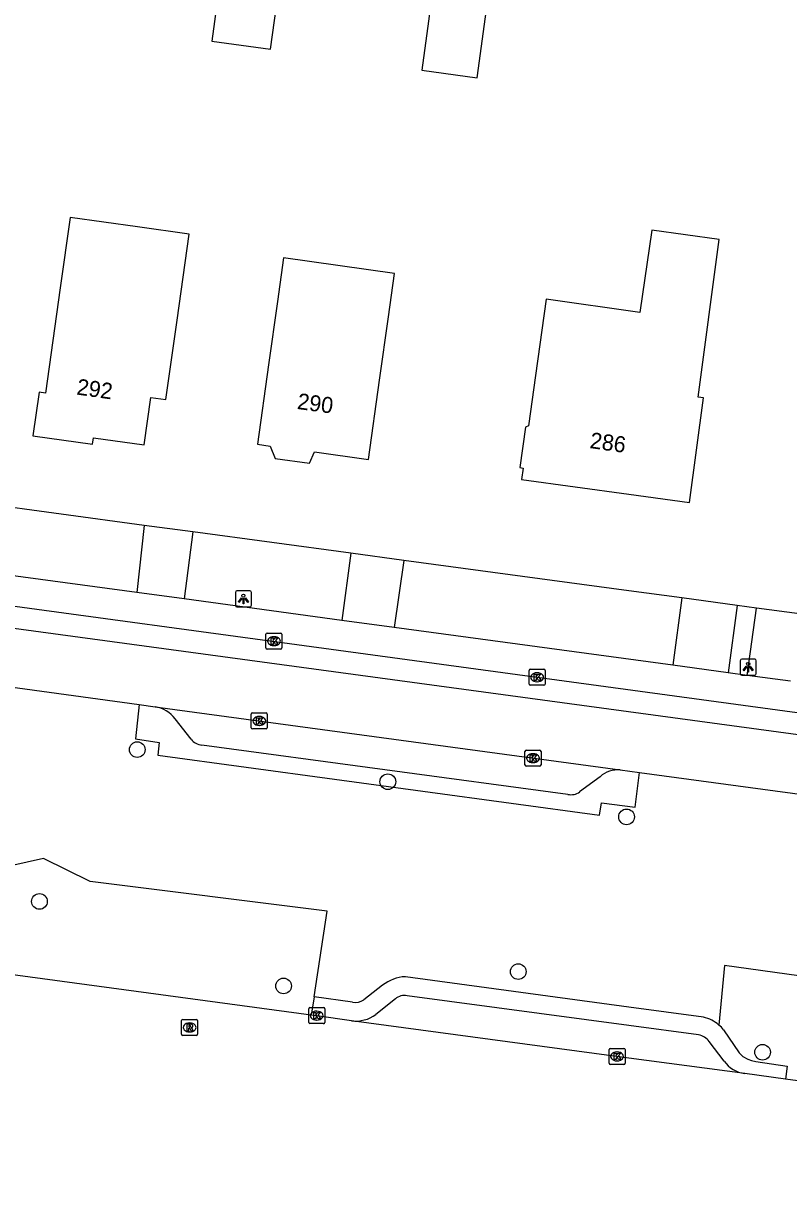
# Model space of a CAD drawing. Extents: x 161696 to 162377, y 380761 to 381673.
# Drawn here: x 161962.2 to 162010, y 380780.2 to 380852.7 of the extents above; entities that cross this region are included whole.
import ezdxf

# ---------------------------------------------------------------- set-up
doc = ezdxf.new("R2010")
doc.units = 0
for name, color, linetype in [('IMGEO_Berm_groen', 7, 'Continuous'), ('IMGEO_Boom', 7, 'Continuous'), ('IMGEO_Kolk', 7, 'Continuous'), ('IMGEO_Lichtpunt', 7, 'Continuous'), ('IMGEO_Pand', 7, 'Continuous'), ('IMGEO_Pand_nummerreeks', 7, 'Continuous'), ('IMGEO_Rijbaan_lokaal_gesloten', 7, 'Continuous'), ('IMGEO_Rioolput', 7, 'Continuous'), ('IMGEO_Voetpad_open', 7, 'Continuous')]:
    doc.layers.add(name, color=color, linetype=linetype)

msp = doc.modelspace()

# ---------------------------------------------------------------- linework, layer by layer
at = {"layer": 'IMGEO_Berm_groen'}
for points in [[(161980.351, 380791.965), (161981.166, 380797.303), (161966.376, 380799.167), (161963.473, 380800.601), (161960.395, 380799.921), (161944.127, 380801.972), (161946.701, 380796.522)], [(162042.929, 380788.793), (162005.959, 380793.923), (162005.619, 380790.206)]]:
    msp.add_lwpolyline(points, dxfattribs=at)
at = {"layer": 'IMGEO_Boom'}
for centre in [(161969.319, 380807.392), (161984.957, 380805.39), (161999.854, 380803.197), (161963.219, 380797.918), (161993.096, 380793.539), (161978.451, 380792.645), (162008.342, 380788.51)]:
    msp.add_circle(centre, 0.489, dxfattribs=at)
at = {"layer": 'IMGEO_Kolk'}
for p, q in [((161977.351, 380813.735), (161977.351, 380814.587)), ((161977.426, 380814.661), (161978.278, 380814.661)), ((161977.839, 380814.441), (161977.864, 380814.441)), ((161978.352, 380814.587), (161978.352, 380813.735)), ((161978.278, 380813.661), (161977.426, 380813.661)), ((161977.862, 380813.881), (161977.837, 380813.881)), ((161993.772, 380811.48), (161993.772, 380812.332)), ((161993.847, 380812.406), (161994.699, 380812.406)), ((161994.26, 380812.186), (161994.285, 380812.186)), ((161994.773, 380812.332), (161994.773, 380811.48)), ((161994.699, 380811.406), (161993.847, 380811.406)), ((161994.283, 380811.626), (161994.258, 380811.626)), ((161976.435, 380808.755), (161976.435, 380809.607)), ((161976.51, 380809.681), (161977.362, 380809.681)), ((161976.923, 380809.461), (161976.948, 380809.461)), ((161977.436, 380809.607), (161977.436, 380808.755)), ((161977.362, 380808.681), (161976.51, 380808.681)), ((161976.946, 380808.901), (161976.921, 380808.901)), ((161993.515, 380806.433), (161993.515, 380807.285)), ((161993.59, 380807.359), (161994.442, 380807.359)), ((161994.003, 380807.139), (161994.028, 380807.139)), ((161994.516, 380807.285), (161994.516, 380806.433)), ((161994.442, 380806.359), (161993.59, 380806.359)), ((161994.026, 380806.579), (161994.001, 380806.579)), ((161980.02, 380790.366), (161980.02, 380791.218)), ((161980.095, 380791.292), (161980.947, 380791.292)), ((161980.508, 380791.072), (161980.533, 380791.072)), ((161981.021, 380791.218), (161981.021, 380790.366)), ((161980.947, 380790.292), (161980.095, 380790.292)), ((161980.531, 380790.512), (161980.506, 380790.512)), ((161998.761, 380787.822), (161998.761, 380788.674)), ((161998.836, 380788.748), (161999.688, 380788.748)), ((161999.249, 380788.528), (161999.274, 380788.528)), ((161999.762, 380788.674), (161999.762, 380787.822)), ((161999.688, 380787.748), (161998.836, 380787.748)), ((161999.272, 380787.968), (161999.247, 380787.968))]:
    msp.add_line(p, q, dxfattribs=at)
for points in [[(161977.351, 380813.735), (161977.351, 380814.587)], [(161977.426, 380814.661), (161978.278, 380814.661)], [(161977.672, 380814.361), (161977.795, 380814.361), (161977.795, 380814.21), (161977.925, 380814.361), (161978.089, 380814.361), (161977.943, 380814.21), (161978.096, 380813.961), (161977.944, 380813.961), (161977.859, 380814.125), (161977.795, 380814.058), (161977.795, 380813.961), (161977.672, 380813.961), (161977.672, 380814.361)], [(161978.352, 380814.587), (161978.352, 380813.735)], [(161978.278, 380813.661), (161977.426, 380813.661)], [(161993.772, 380811.48), (161993.772, 380812.332)], [(161993.847, 380812.406), (161994.699, 380812.406)], [(161994.093, 380812.106), (161994.216, 380812.106), (161994.216, 380811.955), (161994.346, 380812.106), (161994.51, 380812.106), (161994.364, 380811.955), (161994.517, 380811.706), (161994.365, 380811.706), (161994.28, 380811.87), (161994.216, 380811.803), (161994.216, 380811.706), (161994.093, 380811.706), (161994.093, 380812.106)], [(161994.773, 380812.332), (161994.773, 380811.48)], [(161994.699, 380811.406), (161993.847, 380811.406)], [(161976.435, 380808.755), (161976.435, 380809.607)], [(161976.51, 380809.681), (161977.362, 380809.681)], [(161976.756, 380809.381), (161976.879, 380809.381), (161976.879, 380809.23), (161977.009, 380809.381), (161977.173, 380809.381), (161977.027, 380809.23), (161977.18, 380808.981), (161977.028, 380808.981), (161976.943, 380809.145), (161976.879, 380809.078), (161976.879, 380808.981), (161976.756, 380808.981), (161976.756, 380809.381)], [(161977.436, 380809.607), (161977.436, 380808.755)], [(161977.362, 380808.681), (161976.51, 380808.681)], [(161993.515, 380806.433), (161993.515, 380807.285)], [(161993.59, 380807.359), (161994.442, 380807.359)], [(161993.836, 380807.059), (161993.959, 380807.059), (161993.959, 380806.908), (161994.089, 380807.059), (161994.253, 380807.059), (161994.107, 380806.908), (161994.26, 380806.659), (161994.108, 380806.659), (161994.023, 380806.823), (161993.959, 380806.756), (161993.959, 380806.659), (161993.836, 380806.659), (161993.836, 380807.059)], [(161994.516, 380807.285), (161994.516, 380806.433)], [(161994.442, 380806.359), (161993.59, 380806.359)], [(161980.02, 380790.366), (161980.02, 380791.218)], [(161980.095, 380791.292), (161980.947, 380791.292)], [(161980.341, 380790.992), (161980.464, 380790.992), (161980.464, 380790.841), (161980.594, 380790.992), (161980.758, 380790.992), (161980.612, 380790.841), (161980.765, 380790.592), (161980.613, 380790.592), (161980.528, 380790.756), (161980.464, 380790.689), (161980.464, 380790.592), (161980.341, 380790.592), (161980.341, 380790.992)], [(161981.021, 380791.218), (161981.021, 380790.366)], [(161980.947, 380790.292), (161980.095, 380790.292)], [(161998.761, 380787.822), (161998.761, 380788.674)], [(161998.836, 380788.748), (161999.688, 380788.748)], [(161999.082, 380788.448), (161999.205, 380788.448), (161999.205, 380788.297), (161999.335, 380788.448), (161999.499, 380788.448), (161999.353, 380788.297), (161999.506, 380788.048), (161999.354, 380788.048), (161999.269, 380788.212), (161999.205, 380788.145), (161999.205, 380788.048), (161999.082, 380788.048), (161999.082, 380788.448)], [(161999.762, 380788.674), (161999.762, 380787.822)], [(161999.688, 380787.748), (161998.836, 380787.748)]]:
    msp.add_lwpolyline(points, dxfattribs=at)
for centre, start, end in [((161977.428, 380814.585), 91.55205, 178.44795), ((161977.428, 380814.585), 91.55205, 178.44795), ((161978.276, 380814.585), 1.55205, 88.44795), ((161978.276, 380814.585), 1.55205, 88.44795), ((161977.428, 380813.737), 181.55205, 268.44795), ((161977.428, 380813.737), 181.55205, 268.44795), ((161978.276, 380813.737), 271.55205, 358.44795), ((161978.276, 380813.737), 271.55205, 358.44795), ((161993.849, 380812.33), 91.55205, 178.44795), ((161993.849, 380812.33), 91.55205, 178.44795), ((161994.697, 380812.33), 1.55205, 88.44795), ((161994.697, 380812.33), 1.55205, 88.44795), ((161993.849, 380811.482), 181.55205, 268.44795), ((161993.849, 380811.482), 181.55205, 268.44795), ((161994.697, 380811.482), 271.55205, 358.44795), ((161994.697, 380811.482), 271.55205, 358.44795), ((161976.512, 380809.605), 91.55205, 178.44795), ((161976.512, 380809.605), 91.55205, 178.44795), ((161977.36, 380809.605), 1.55205, 88.44795), ((161977.36, 380809.605), 1.55205, 88.44795), ((161976.512, 380808.757), 181.55205, 268.44795), ((161976.512, 380808.757), 181.55205, 268.44795), ((161977.36, 380808.757), 271.55205, 358.44795), ((161977.36, 380808.757), 271.55205, 358.44795), ((161993.592, 380807.283), 91.55205, 178.44795), ((161993.592, 380807.283), 91.55205, 178.44795), ((161994.44, 380807.283), 1.55205, 88.44795), ((161994.44, 380807.283), 1.55205, 88.44795), ((161993.592, 380806.435), 181.55205, 268.44795), ((161993.592, 380806.435), 181.55205, 268.44795), ((161994.44, 380806.435), 271.55205, 358.44795), ((161994.44, 380806.435), 271.55205, 358.44795), ((161980.097, 380791.216), 91.55205, 178.44795), ((161980.097, 380791.216), 91.55205, 178.44795), ((161980.945, 380791.216), 1.55205, 88.44795), ((161980.945, 380791.216), 1.55205, 88.44795), ((161980.097, 380790.368), 181.55205, 268.44795), ((161980.097, 380790.368), 181.55205, 268.44795), ((161980.945, 380790.368), 271.55205, 358.44795), ((161980.945, 380790.368), 271.55205, 358.44795), ((161998.838, 380788.672), 91.55205, 178.44795), ((161998.838, 380788.672), 91.55205, 178.44795), ((161999.686, 380788.672), 1.55205, 88.44795), ((161999.686, 380788.672), 1.55205, 88.44795), ((161998.838, 380787.824), 181.55205, 268.44795), ((161998.838, 380787.824), 181.55205, 268.44795), ((161999.686, 380787.824), 271.55205, 358.44795), ((161999.686, 380787.824), 271.55205, 358.44795)]:
    msp.add_arc(centre, 0.0765, start, end, dxfattribs=at)
for centre, major_axis, ratio, start_param, end_param in [((161977.838, 380814.161), (-0.387, 0.002), 0.722429, 4.712389, 7.853982), ((161977.863, 380814.161), (-0.39, 0.002), 0.717154, 1.570796, 4.712389), ((161994.259, 380811.906), (-0.387, 0.002), 0.722429, 4.712389, 7.853982), ((161994.284, 380811.906), (-0.39, 0.002), 0.717154, 1.570796, 4.712389), ((161976.922, 380809.181), (-0.387, 0.002), 0.722429, 4.712389, 7.853982), ((161976.947, 380809.181), (-0.39, 0.002), 0.717154, 1.570796, 4.712389), ((161994.002, 380806.859), (-0.387, 0.002), 0.722429, 4.712389, 7.853982), ((161994.027, 380806.859), (-0.39, 0.002), 0.717154, 1.570796, 4.712389), ((161980.507, 380790.792), (-0.387, 0.002), 0.722429, 4.712389, 7.853982), ((161980.532, 380790.792), (-0.39, 0.002), 0.717154, 1.570796, 4.712389), ((161999.248, 380788.248), (-0.387, 0.002), 0.722429, 4.712389, 7.853982), ((161999.273, 380788.248), (-0.39, 0.002), 0.717154, 1.570796, 4.712389)]:
    msp.add_ellipse(centre, major_axis=major_axis, ratio=ratio, start_param=start_param, end_param=end_param, dxfattribs=at)
at = {"layer": 'IMGEO_Lichtpunt'}
for p, q in [((161975.444, 380817.204), (161975.444, 380816.397)), ((161975.444, 380817.204), (161975.444, 380816.397)), ((161976.346, 380817.299), (161975.538, 380817.299)), ((161976.346, 380817.299), (161975.538, 380817.299)), ((161976.44, 380816.397), (161976.44, 380817.204)), ((161976.44, 380816.397), (161976.44, 380817.204)), ((161975.538, 380816.303), (161976.346, 380816.303)), ((161975.538, 380816.303), (161976.346, 380816.303)), ((162006.949, 380812.94), (162006.949, 380812.133)), ((162006.949, 380812.94), (162006.949, 380812.133)), ((162007.851, 380813.035), (162007.043, 380813.035)), ((162007.851, 380813.035), (162007.043, 380813.035)), ((162007.945, 380812.133), (162007.945, 380812.94)), ((162007.945, 380812.133), (162007.945, 380812.94)), ((162007.043, 380812.039), (162007.851, 380812.039)), ((162007.043, 380812.039), (162007.851, 380812.039))]:
    msp.add_line(p, q, dxfattribs=at)
for points in [[(161975.818, 380816.868), (161975.857, 380816.84), (161975.669, 380816.578), (161975.631, 380816.605), (161975.818, 380816.868)], [(161975.92, 380816.82), (161975.967, 380816.82), (161975.967, 380816.498), (161975.92, 380816.498), (161975.92, 380816.82)], [(161976.03, 380816.84), (161976.068, 380816.867), (161976.255, 380816.605), (161976.216, 380816.577), (161976.03, 380816.84)], [(162007.323, 380812.604), (162007.362, 380812.576), (162007.174, 380812.314), (162007.136, 380812.341), (162007.323, 380812.604)], [(162007.425, 380812.556), (162007.472, 380812.556), (162007.472, 380812.234), (162007.425, 380812.234), (162007.425, 380812.556)], [(162007.535, 380812.576), (162007.573, 380812.603), (162007.76, 380812.341), (162007.721, 380812.313), (162007.535, 380812.576)]]:
    msp.add_lwpolyline(points, dxfattribs=at)
for centre in [(161975.943, 380817.002), (162007.448, 380812.738)]:
    msp.add_circle(centre, 0.0994, dxfattribs=at)
for centre, start, end in [((161975.538, 380817.204), 90, 180), ((161975.538, 380817.204), 90, 180), ((161976.346, 380817.204), 0, 90), ((161976.346, 380817.204), 0, 90), ((161975.538, 380816.397), 180, 270), ((161975.538, 380816.397), 180, 270), ((161976.346, 380816.397), 270, 0), ((161976.346, 380816.397), 270, 360), ((162007.043, 380812.94), 90, 180), ((162007.043, 380812.94), 90, 180), ((162007.851, 380812.94), 0, 90), ((162007.851, 380812.94), 0, 90), ((162007.043, 380812.133), 180, 270), ((162007.043, 380812.133), 180, 270), ((162007.851, 380812.133), 270, 0), ((162007.851, 380812.133), 270, 360)]:
    msp.add_arc(centre, 0.0946, start, end, dxfattribs=at)
at = {"layer": 'IMGEO_Pand'}
for points in [[(161977.634, 380851.095), (161978.48, 380857.235), (161974.814, 380857.747), (161973.969, 380851.607), (161977.634, 380851.095)], [(161990.529, 380849.306), (161991.36, 380855.436), (161987.912, 380855.918), (161987.081, 380849.788), (161990.529, 380849.306)], [(161971.806, 380834.194), (161972.558, 380839.55), (161969.325, 380840.004), (161965.132, 380840.593), (161964.516, 380836.203), (161963.593, 380829.634), (161963.194, 380829.69), (161962.813, 380826.98), (161966.534, 380826.458), (161966.59, 380826.857), (161969.76, 380826.411), (161970.176, 380829.373), (161971.111, 380829.242), (161971.806, 380834.194)], [(162001.423, 380839.8), (162000.684, 380834.664), (161994.84, 380835.505), (161994.172, 380830.733), (161993.732, 380827.592), (161993.549, 380827.518), (161993.193, 380824.987), (161993.405, 380824.957), (161993.306, 380824.253), (162000, 380823.327), (162003.783, 380822.804), (162004.663, 380829.338), (162004.314, 380829.385), (162005.639, 380839.233), (162001.423, 380839.8)], [(161984.446, 380830.454), (161984.999, 380834.395), (161985.38, 380837.107), (161978.444, 380838.082), (161978.062, 380835.362), (161977.519, 380831.395), (161976.823, 380826.443), (161977.607, 380826.333), (161977.918, 380825.562), (161980.069, 380825.26), (161980.383, 380825.975), (161983.75, 380825.502), (161984.446, 380830.454)]]:
    msp.add_lwpolyline(points, dxfattribs=at)
at = {"layer": 'IMGEO_Rijbaan_lokaal_gesloten'}
for points in [[(162234.771, 380780.432), (162229.289, 380780.178), (162226.418, 380780.403), (162192.055, 380785.129), (162178.941, 380786.895), (162173.589, 380787.538), (162153.114, 380788.982), (161814.137, 380834.931)], [(161920.649, 380821.91), (162019.525, 380808.483)], [(161940.415, 380814.186), (161969.449, 380810.213)], [(161969.449, 380810.213), (161970.442, 380810.065)], [(161970.442, 380810.065), (161999.463, 380806.128)], [(161999.463, 380806.128), (162000.665, 380805.971)], [(162000.665, 380805.971), (162035.924, 380801.201)], [(161980.175, 380790.815), (161955.234, 380794.192), (161946.543, 380795.38)], [(161982.699, 380790.464), (161980.517, 380790.791), (161980.175, 380790.815)], [(162007.226, 380787.18), (162000, 380788.148), (161982.699, 380790.464)], [(162009.782, 380786.834), (162007.226, 380787.18)], [(162034.725, 380783.435), (162018.39, 380785.673), (162009.782, 380786.834)]]:
    msp.add_lwpolyline(points, dxfattribs=at)
at = {"layer": 'IMGEO_Rioolput'}
for p, q in [((161972.087, 380789.628), (161972.087, 380790.48)), ((161972.162, 380790.554), (161973.014, 380790.554)), ((161972.575, 380790.334), (161972.6, 380790.334)), ((161973.088, 380790.48), (161973.088, 380789.628)), ((161973.014, 380789.554), (161972.162, 380789.554)), ((161972.598, 380789.774), (161972.573, 380789.774))]:
    msp.add_line(p, q, dxfattribs=at)
for points in [[(161972.087, 380789.628), (161972.087, 380790.48)], [(161972.162, 380790.554), (161973.014, 380790.554)], [(161972.676, 380790.252), (161972.424, 380790.254), (161972.424, 380789.854)], [(161973.088, 380790.48), (161973.088, 380789.628)], [(161973.014, 380789.554), (161972.162, 380789.554)], [(161972.424, 380789.854), (161972.548, 380789.854), (161972.548, 380790.016), (161972.559, 380790.016)], [(161972.602, 380790.173), (161972.548, 380790.173), (161972.548, 380790.092)], [(161972.548, 380790.092), (161972.6, 380790.092)], [(161972.606, 380789.987), (161972.677, 380789.854), (161972.817, 380789.854), (161972.752, 380789.98)]]:
    msp.add_lwpolyline(points, dxfattribs=at)
for centre, radius, start, end in [((161972.164, 380790.478), 0.0765, 91.55205, 178.44795), ((161972.164, 380790.478), 0.0765, 91.55205, 178.44795), ((161972.675, 380790.142), 0.109, 350.36119, 89.41601), ((161973.012, 380790.478), 0.0765, 1.55205, 88.44795), ((161973.012, 380790.478), 0.0765, 1.55205, 88.44795), ((161972.164, 380789.63), 0.0765, 181.55205, 268.44795), ((161972.164, 380789.63), 0.0765, 181.55205, 268.44795), ((161972.558, 380789.963), 0.0533, 26.02933, 88.69889), ((161972.584, 380790.281), 0.19, 274.7715, 282.96867), ((161972.608, 380790.077), 0.0964, 77.00612, 93.18647), ((161972.622, 380790.134), 0.0378, 276.66336, 79.67722), ((161972.673, 380790.142), 0.112, 277.58423, 350.98172), ((161972.657, 380789.927), 0.108, 29.51342, 73.79051), ((161973.012, 380789.63), 0.0765, 271.55205, 358.44795), ((161973.012, 380789.63), 0.0765, 271.55205, 358.44795)]:
    msp.add_arc(centre, radius, start, end, dxfattribs=at)
for centre, major_axis, ratio, start_param, end_param in [((161972.574, 380790.054), (-0.387, 0.002), 0.722429, 4.712389, 7.853982), ((161972.599, 380790.054), (-0.39, 0.002), 0.717154, 1.570796, 4.712389)]:
    msp.add_ellipse(centre, major_axis=major_axis, ratio=ratio, start_param=start_param, end_param=end_param, dxfattribs=at)
at = {"layer": 'IMGEO_Voetpad_open'}
for points in [[(161969.747, 380821.384), (161959.367, 380822.785)], [(161969.747, 380821.384), (161969.295, 380817.193)], [(161972.782, 380820.974), (161969.747, 380821.384)], [(161972.782, 380820.974), (161972.239, 380816.792)], [(161982.64, 380819.644), (161972.782, 380820.974)], [(161982.64, 380819.644), (161982.089, 380815.455)], [(161985.956, 380819.196), (161982.64, 380819.644)], [(161969.295, 380817.193), (161958.799, 380818.621)], [(161985.956, 380819.196), (161985.346, 380815.014)], [(162003.3, 380816.856), (162000, 380817.301), (161985.956, 380819.196)], [(161972.239, 380816.792), (161969.295, 380817.193)], [(161982.089, 380815.455), (161972.239, 380816.792)], [(162003.3, 380816.856), (162002.733, 380812.656)], [(162006.759, 380816.389), (162003.3, 380816.856)], [(162006.759, 380816.389), (162006.192, 380812.187)], [(162007.953, 380816.216), (162006.759, 380816.389)], [(162007.385, 380812.025), (162007.953, 380816.216)], [(162010.645, 380815.865), (162007.953, 380816.216)], [(161985.346, 380815.014), (161982.089, 380815.455)], [(162002.733, 380812.656), (161985.346, 380815.014)], [(162006.192, 380812.187), (162002.733, 380812.656)], [(162007.385, 380812.025), (162006.192, 380812.187)], [(162010.075, 380811.66), (162007.385, 380812.025)], [(161969.449, 380810.213), (161969.203, 380808.068), (161970.679, 380807.83), (161970.596, 380807.038), (161998.17, 380803.296), (161998.295, 380804.077), (162000.388, 380803.799), (162000.665, 380805.971)], [(161972.68, 380808.038), (161971.676, 380809.315)], [(161996.19, 380804.597), (161973.355, 380807.679)], [(161998.199, 380805.701), (161996.928, 380804.748)], [(162004.657, 380790.7), (162000, 380791.331), (161986.05, 380793.223)], [(161984.634, 380792.695), (161983.454, 380791.774)], [(161980.351, 380791.965), (161980.175, 380790.815)], [(161982.754, 380791.63), (161980.351, 380791.965)], [(161985.428, 380791.835), (161984.205, 380790.861)], [(162004.353, 380789.598), (162000, 380790.182), (161986.168, 380792.038)], [(162005.906, 380789.91), (162006.873, 380788.479), (162007.116, 380788.236), (162007.416, 380788.074), (162007.654, 380787.992), (162007.916, 380787.941), (162009.877, 380787.648), (162009.782, 380786.834)], [(162005.942, 380787.96), (162005.01, 380789.187)]]:
    msp.add_lwpolyline(points, dxfattribs=at)
for centre, radius, start, end in [((161970.147, 380808.19), 1.898, 36.3517, 81.06754), ((161973.436, 380808.646), 0.97, 218.78418, 265.2031), ((161999.334, 380804.427), 1.706, 85.64887, 131.68276), ((161996.38, 380805.55), 0.971, 258.74895, 304.37808), ((161986.171, 380790.735), 2.491, 92.78787, 128.11123), ((161982.917, 380792.613), 0.996, 260.60601, 302.64278), ((161985.991, 380791.234), 0.823, 77.56694, 133.11357), ((161982.942, 380792.596), 2.146, 263.49356, 306.04225), ((162004.122, 380788.474), 2.289, 49.15709, 76.48069), ((162004.141, 380788.529), 1.09, 37.15323, 78.78898), ((162004.167, 380788.511), 2.232, 38.81663, 49.41451), ((162007.498, 380789.075), 1.915, 215.62457, 261.82002)]:
    msp.add_arc(centre, radius, start, end, dxfattribs=at)

# ---------------------------------------------------------------- texts
at = {"layer": 'IMGEO_Pand_nummerreeks'}
for s, rotation, p in [('292', 351.99139, (161965.497, 380829.555)), ('290', 352.26399, (161979.263, 380828.654)), ('286', 352.12578, (161997.525, 380826.214))]:
    msp.add_text(s, height=1, rotation=rotation, dxfattribs=at).set_placement(p)

doc.saveas('drawing.dxf')
